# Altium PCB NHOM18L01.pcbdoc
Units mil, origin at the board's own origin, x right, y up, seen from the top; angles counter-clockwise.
Board outline 2892.2 x 1700 mil, 2 copper layers (Top Layer, Bottom Layer); 35 components, 50 nets, 178 pads, 21 vias.
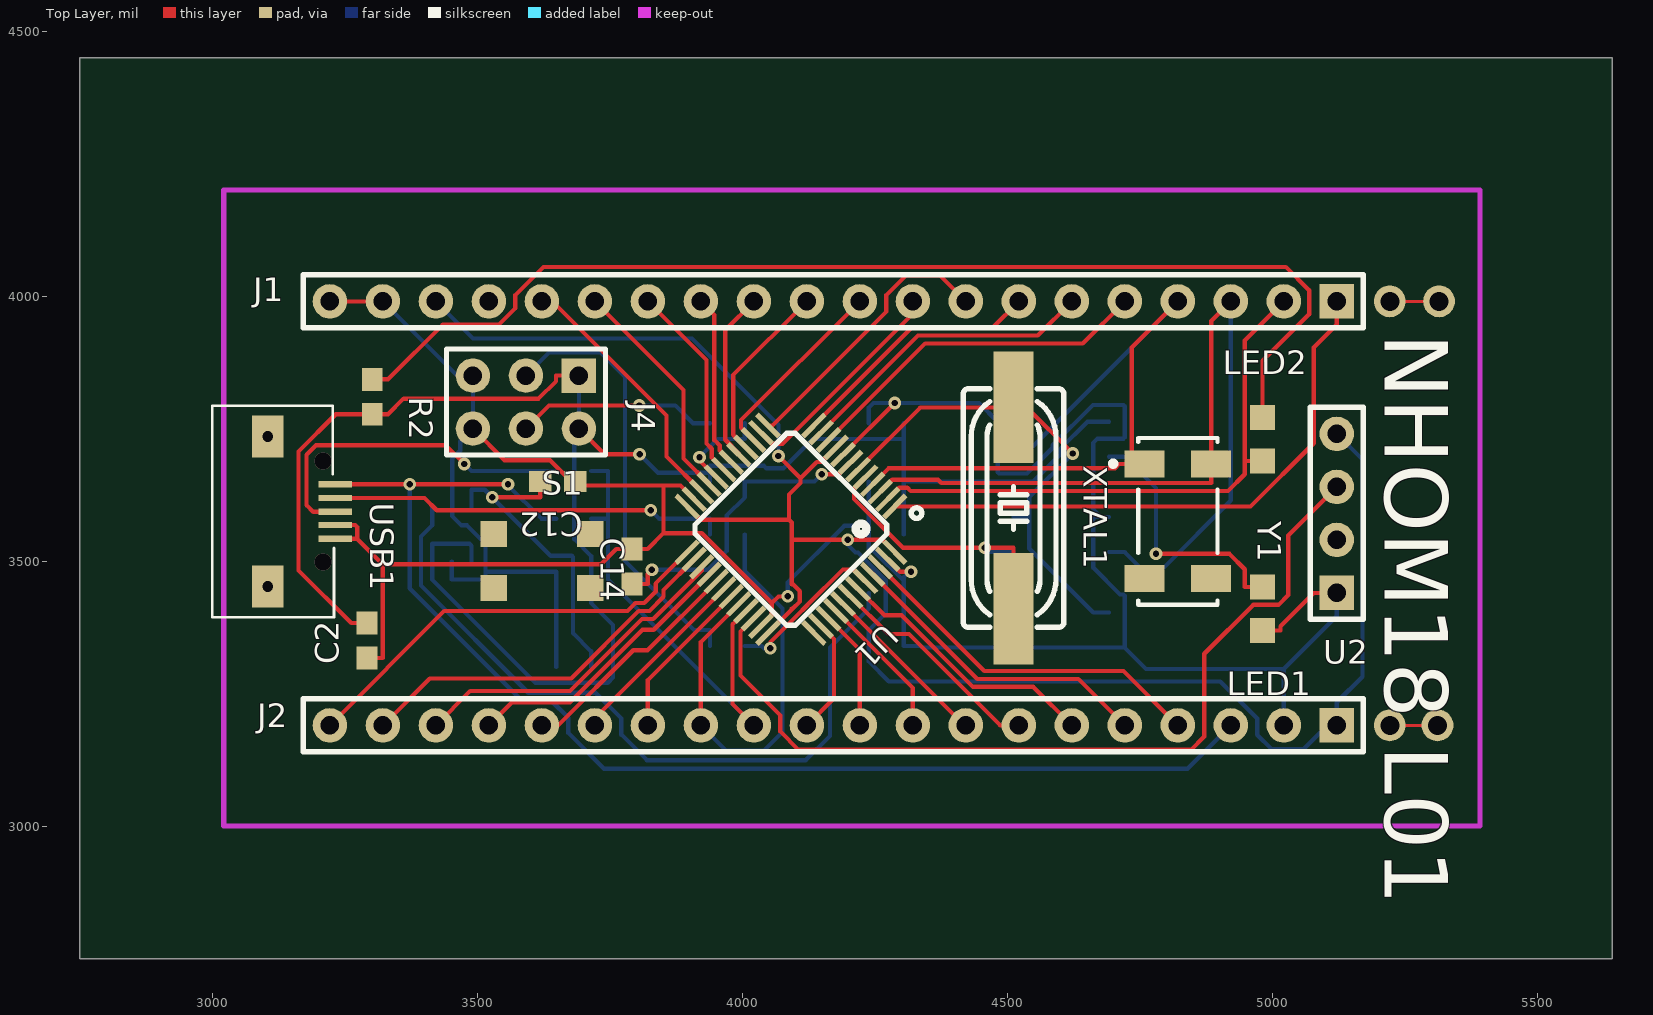
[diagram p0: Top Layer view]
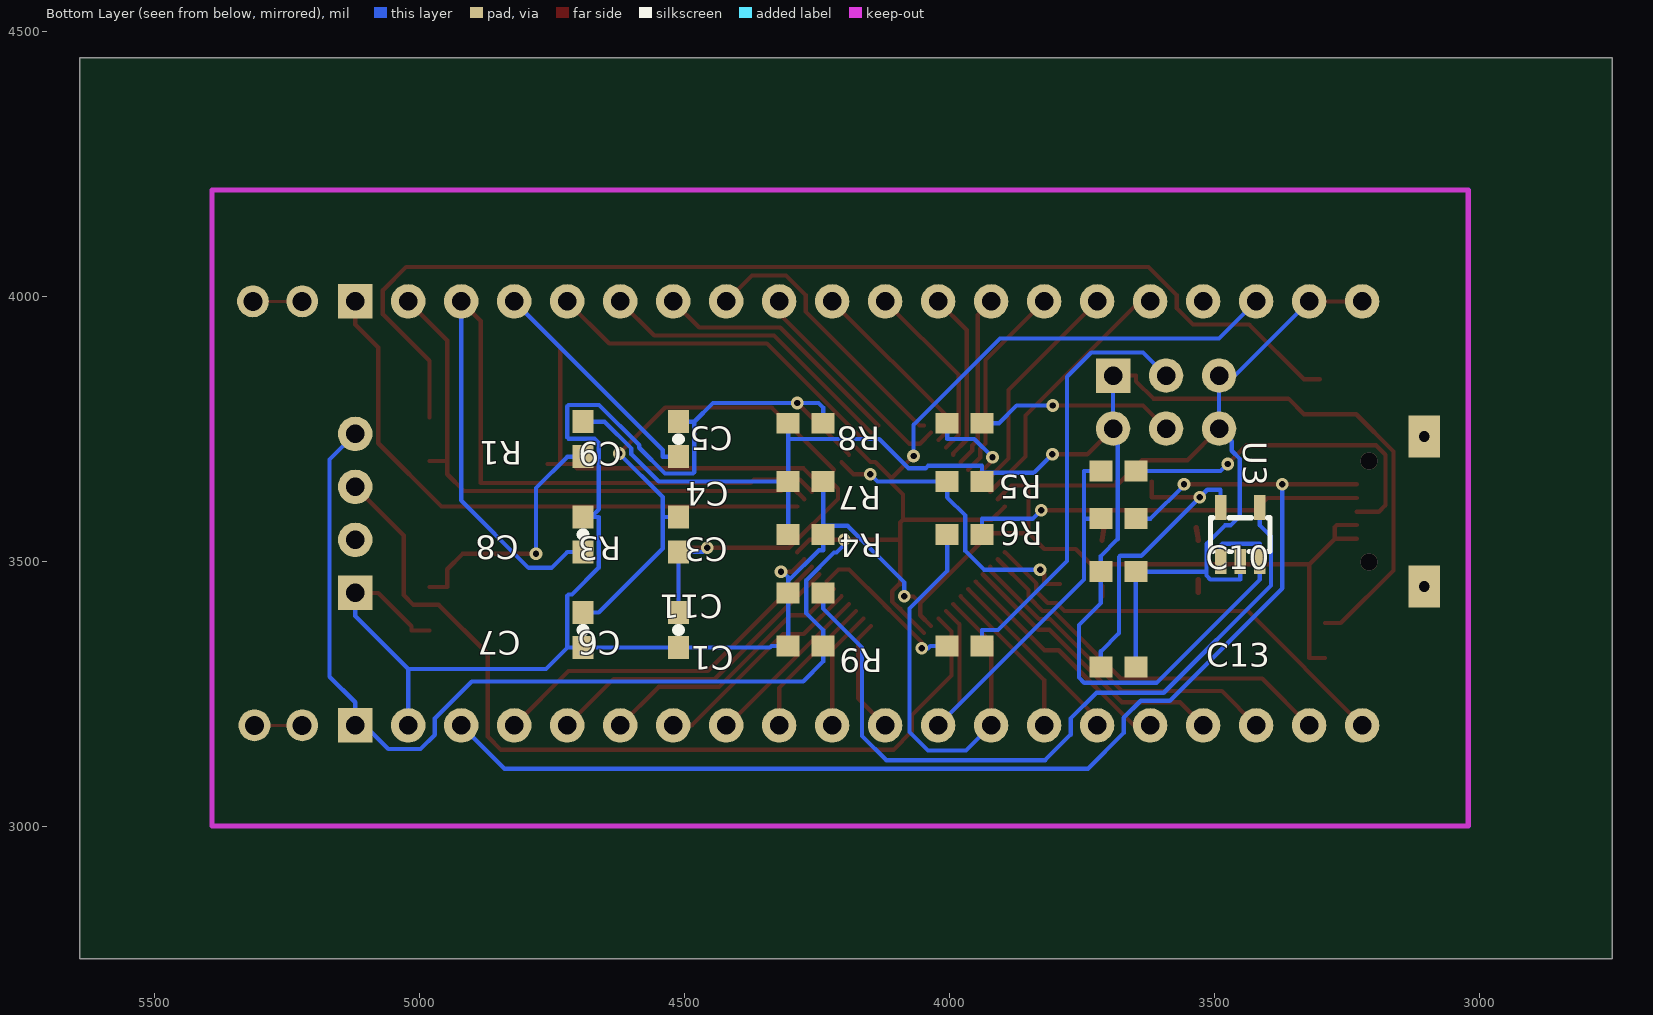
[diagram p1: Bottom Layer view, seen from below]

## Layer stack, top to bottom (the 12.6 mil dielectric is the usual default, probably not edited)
Top Layer: signal copper (thickness not stored)
Dielectric: dielectric 12.6, FR-4, Dk 4.8
Bottom Layer: signal copper (thickness not stored)

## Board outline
5642.2,2750 2750,2750 2750,4450 5642.2,4450

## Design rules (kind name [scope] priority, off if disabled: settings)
Clearance Default [All] p1: gap=7 ignorepadtopadclearanceinfootprint=FALSE except(0: Fill-Fill; 6: Track-Track Track-SMDPad SMDPad-SMDPad Track-THPad SMDPad-THPad THPad-THPad Track-Via SMDPad-Via THPad-Via Via-Via Track-Fill SMDPad-Fill THPad-Fill Via-Fill Track-Poly SMDPad-Poly THPad-Poly Via-Poly Fill-Poly Poly-Poly Track-Text SMDPad-Text THPad-Text Via-Text Fill-Text Poly-Text Text-Text Track-Hole SMDPad-Hole THPad-Hole Via-Hole Fill-Hole Poly-Hole Text-Hole)
DiffPairsRouting differentialPair [All] p1: maxuncoupledlength=10 minlimit=6 maxlimit=50 mostfreqgap=6 toplayer_minwidth=5 toplayer_prefwidth=10 toplayer_maxwidth=100 bottomlayer_minwidth=5 bottomlayer_prefwidth=10 bottomlayer_maxwidth=100
PasteMaskExpansion Common [All] p1:
PlaneConnect Default [All] p1: planeconnectstyle=Relief reliefexpansion=20 reliefentries=4 reliefconductorwidth=0 reliefairgap=10
PolygonConnect Default [All] p1: connectstyle=Relief reliefentries=4 polygonreliefangle="90 Angle" airgapwidth=10
RoutingVias Default [All] p1: viastyle="Through Hole" holewidth=12 minholewidth=12 maxholewidth=2362 width=24 minwidth=24 maxwidth=3938
SolderMaskExpansion Common [All] p1: useseparateexpansions=TRUE expansion=2 expansionbottom=2
Width Default [All] p1: maxlimit=1000 minlimit=6 preferedwidth=6

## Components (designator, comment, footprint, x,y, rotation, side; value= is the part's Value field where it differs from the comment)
C1 "100nF" 0603 4272.2,3340 r180 bottom
C2 "100nF" 0603 3292.2,3350 r90 top
C3 "100nF" 0603 4272.2,3550 r0 bottom
C4 "100nF" 0603 4272.2,3650 r0 bottom
C5 "100nF" 0603 4272.2,3760 r0 bottom
C6 "CAP" 0603-CAP 4512.2,3370 r90 bottom
C7 "CAP" 0603-CAP 4692.2,3370 r90 bottom
C8 "CAP" 0603-CAP 4692.2,3550 r270 bottom
C9 "CAP" 0603-CAP 4512.2,3730 r270 bottom
C10 "105" 0603 3682.2,3480 r180 bottom
C11 "223" 0603 4272.2,3440 r180 bottom
C12 "106" 0603 3652.2,3650 r180 top
C13 "104" 0603 3682.2,3300 r0 bottom
C14 "105" 0603 3792.2,3490 r270 top
J1 "HEADER-20P-2.54" H20-2.54 4172.2,3990 r270 top
J2 "HEADER-20P-2.54" H20-2.54 4172.2,3190 r270 top
J4 "F185-1203A1BSYA1" H2X3-2.54 3592.2,3800 r270 top
LED1 "LEDCHIPLED_0805" CHIPLED_0805 4982.2,3410 r180 top
LED2 "LEDCHIPLED_0805" CHIPLED_0805 4982.2,3730 r180 top
R1 "510Ω" 0603 4692.2,3730 r90 bottom
R2 "510Ω" 0603 3302.2,3810 r270 top
R3 "1M" 0603 4512.2,3550 r270 bottom
R4 "20R" 0603 3972.2,3550 r0 bottom
R5 "20R" 0603 3682.2,3670 r0 bottom
R6 "4.7K" 0603 3682.2,3580 r0 bottom
R7 "10K" 0603 3972.2,3650 r180 bottom
R8 "100K" 0603 3972.2,3760 r180 bottom
R9 "100K" 0603 3972.2,3340 r0 bottom
S1 "2P-SW-SMD" 2PSW-SMD 3622.2,3500 r0 top
U1 "IC_UC_STM32" LQFP48 4092.2,3560 r225 top
U2 "header4" H4-2.54 5122.2,3590 r180 top
U3 "RT9193-33GB" SOT-23-5 3452.2,3550 r180 bottom
USB1 "USB-Micro-1" MicroUSB 3202.2,3690 r270 top
XTAL1 "8M" HC-49U 4512.2,3600 r270 top
Y1 "RSM200S32.768" RSM200S 4822.2,3580 r270 top

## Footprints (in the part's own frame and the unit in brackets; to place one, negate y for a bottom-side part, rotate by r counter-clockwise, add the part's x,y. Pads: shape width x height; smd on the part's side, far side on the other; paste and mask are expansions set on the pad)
2PSW-SMD [mil]
  rect 50x25 smd: 1(-91,63) 2(91,63) 3(91,-63) 4(-91,-63) P$1(-91,39) P$2(91,39) P$3(91,-39) P$4(-91,-39)
  Top Layer lines w10: -91,-59 -91,-35 ; -91,39 -87,63 ; 87,63 91,39 ; 91,-67 91,-47
0603 [mil]
  rect 43.3x39.4 smd: 1(-33,0) 2(33,0)
0603-CAP [mil]
  rect 43.3x39.4 smd: 1(-33,0) 2(33,0)
  silkscreen extent 0,-1 0,1
CHIPLED_0805 [mil]
  rect 47.2x47.2 smd: A(0,-41) C(0,41)
H2X3-2.54 [mil]
  rect 65x65 hole 35: 1(-50,100)
  round 65 hole 35: 2(-50,0) 3(-50,-100) 4(50,-100) 5(50,0) 6(50,100)
  silkscreen extent -100,-150 100,150
H4-2.54 [mil]
  rect 65x65 hole 35: 1(0,150)
  round 65 hole 35: 2(0,50) 3(0,-50) 4(0,-150)
  silkscreen extent -50,-200 50,200
H20-2.54 [mil]
  rect 65x65 hole 35: 1(0,950)
  round 65 hole 35: 2(0,850) 3(0,750) 4(0,650) 5(0,550) 6(0,450) 7(0,350) 8(0,250) 9(0,150) 10(0,50) 11(0,-50) 12(0,-150) 13(0,-250) 14(0,-350) 15(0,-450) 16(0,-550) 17(0,-650) 18(0,-750) 19(0,-850) 20(0,-950)
  silkscreen extent -50,-1000 50,1000
HC-49U [mil]
  rect 210x76 smd: 1(-190,0) 2(190,0)
  silkscreen extent -225,-95 225,95
LQFP48 [mil]
  rect 59.1x10 smd: 1(-169,108.02) 2(-169.01,89.02) 3(-169.01,69.02) 4(-169,49.02) 5(-169.01,30.02) 6(-169.01,10.02) 7(-169.01,-9.98) 8(-169,-29.98) 9(-169.01,-48.98) 10(-169.01,-68.98) 11(-169,-88.98) 12(-169.01,-107.98) 25(169,-107.98) 26(169,-88.98) 27(169,-68.99) 28(169,-48.97) 29(169,-29.98) 30(169,-9.98) 31(168.99,10.02) 32(169,30.02) 33(169,49.02) 34(168.99,69.02) 35(169,89.02) 36(169,108.02)
  rect 10x59.1 smd: 13(-108,-168.98) 14(-89,-168.98) 15(-69.01,-168.98) 16(-49,-168.98) 17(-30,-168.98) 18(-10.01,-168.98) 19(10,-168.98) 20(30,-168.98) 21(49,-168.98) 22(69,-168.98) 23(89,-168.98) 24(108,-168.98) 37(108,169.02) 38(89,169.02) 39(68.99,169.02) 40(49,169.02) 41(30,169.02) 42(9.99,169.02) 43(-10.01,169.02) 44(-30,169.02) 45(-49,169.02) 46(-69.01,169.02) 47(-89,169.02) 48(-108,169.02)
  silkscreen extent -199,-134 134,156
MicroUSB [mil]
  rect 12x63 smd: 1(45,30) 2(71,30) 3(97,30) 4(122,30) 5(148,30)
  rect 79x59 hole 20: 6(-45,-97) 6(238,-97)
  silkscreen extent -103,-202 296,28
RSM200S [mil]
  rect 51.5x75.5 smd: 1(-103,-63) 2(113,-63) 3(113,63) 4(-103,63)
  silkscreen extent -152,-127 162,75
SOT-23-5 [mil]
  rect 21.7x47.2 smd: 1(-37,-51) 2(0,-51) 3(37,-51) 4(37,51) 5(-37,51)
  silkscreen extent -56,-32 56,32

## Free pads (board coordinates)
  round 60 hole 36: 1(5222.2,3190) 1(5222.2,3990) 2(5312.2,3190) 2(5315.06,3990)

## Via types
v1: diameter 24, hole 12, Top Layer to Bottom Layer, 19 vias
v2: diameter 31.5, hole 31.5, Top Layer to Bottom Layer, 2 vias

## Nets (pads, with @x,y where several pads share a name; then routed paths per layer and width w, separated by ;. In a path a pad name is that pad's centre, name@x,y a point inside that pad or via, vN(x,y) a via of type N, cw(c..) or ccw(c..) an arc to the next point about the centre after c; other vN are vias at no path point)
5V: J2.3 R6.1 USB1.1 | length 2382.8
  Top Layer w8: USB1.1 v1(3372.8,3645) v1(3558.4,3645)
  Bottom Layer w8: v1(3372.8,3645) 3372.8,3448.83 3585.09,3236.54 3639.98,3236.54 3672.2,3204.32 3672.2,3175.39 3739.53,3108.06 4840.26,3108.06 J2.3 ; v1(3558.4,3645) 3558.43,3642.92 3621.35,3580 3635.3,3580 3642.81,3580 3646.03,3580 R6.1
BOOT0: R9.2 U1.44 | length 307.4
  Top Layer w8: v1(4053.4,3335.5) 4053.4,3347.19 4101.59,3395.38 4101.75,3395.38 4124.01,3417.64 4124.01,3417.8 4190.48,3484.27 4210.38,3484.27 U1.44@4232.95,3461.7
  Bottom Layer w8: R9.2 4036.91,3340 4041.37,3335.54 v1(4053.4,3335.5)
BOOT1: R8.1 U1.20 | length 180.3
  Top Layer w8: v1(3919.8,3696.1) 3919.83,3689.92 U1.20@3951.5,3658.25
  Bottom Layer w8: v1(3919.8,3696.1) 3954.01,3730.29 4005.25,3730.29 R8.1
C13_2: C12.2 C13.2 U3.5 | length 620.2
  Top Layer w8: v1(3528.7,3620.3) 3619.25,3620.29 C12.2
  Bottom Layer w8: U3.5 3489.25,3634.61 3514.35,3634.61 v1(3528.7,3620.3) 3638.79,3510.17 3678.61,3510.17 3680.92,3507.86 3680.92,3364.04 3715.25,3329.71 C13.2
J4_2: J4.2 R9.1 | length 815.4
  Bottom Layer w8: J4.2 3635.72,3893.52 3733.39,3893.52 3779.12,3847.79 3779.12,3500.13 3909.54,3369.71 3939.25,3369.71 R9.1
J4_5: J4.5 R8.2 | length 379
  Top Layer w8: J4.5 3635.72,3793.52 v1(3805.8,3793.5)
  Bottom Layer w8: v1(3805.8,3793.5) 3874.07,3793.52 3907.59,3760 R8.2
LED1_A: LED1.A R1.1 | length 484.4
  Top Layer w8: v1(4781,3513.6) 4919.58,3513.62 4948.59,3484.61 4948.59,3451 LED1.A
  Bottom Layer w8: R1.1 4721.91,3696.95 4780.98,3637.88 v1(4781,3513.6)
OSCIN: C6.2 R3.2 U1.5 XTAL1.2 | length 681.9
  Top Layer w8: U1.5@4232.95,3658.25 4211.3,3636.6 4211.3,3617.36 4303.65,3525.01 v1(4457.8,3525) 4512.2,3525.01 XTAL1.2
  Bottom Layer w8: v1(4457.8,3525) 4465.84,3516.95 4482.49,3516.95 R3.2@4497.35,3516.95 ; C6.2 4512.2,3502.1 R3.2@4497.35,3516.95 ; R3.2 R3.2@4497.35,3516.95
OSCOUT: C7.2 R3.1 U1.6 XTAL1.1 | length 933.5
  Top Layer w8: U1.6 4336.38,3790 XTAL1.1 4537.09,3790 v1(4624.1,3703)
  Bottom Layer w8: R3.1 4541.91,3582.95 ; v1(4624.1,3703) 4541.91,3620.74 4541.91,3582.95 ; C7.2 4662.49,3402.95 4541.91,3523.53 4541.91,3582.95
PA0: J1.5 U1.10 | length 667.7
  Top Layer w8: U1.10@4162.95,3728.25 4345.44,3910.74 4642.94,3910.74 J1.5
PA1: J1.6 U1.11 | length 576
  Top Layer w8: U1.11 4332.11,3925.75 4557.95,3925.75 J1.6
PA2: J1.7 U1.12 | length 483.8
  Top Layer w8: U1.12@4135.35,3755.85 4320.26,3940.76 4472.96,3940.76 J1.7
PA3: J1.8 U1.13 | length 528.9
  Top Layer w8: U1.13@4049.08,3755.85 4057.21,3755.85 4272.2,3970.84 4272.2,4001.99 4309.16,4038.95 4373.25,4038.95 J1.8
PA4: J1.9 U1.14 | length 420.1
  Top Layer w8: U1.14 4056.88,3721.19 4076.2,3721.19 4322.2,3967.19 J1.9
PA5: J1.10 U1.15 | length 364.2
  Top Layer w8: U1.15@4021.53,3728.25 3998.17,3751.61 3998.17,3765.97 J1.10
PA6: J1.11 U1.16 | length 343.5
  Top Layer w8: U1.16@4007.35,3714.15 3983.15,3738.35 3983.15,3850.95 J1.11
PA7: J1.12 U1.17 | length 322.4
  Top Layer w8: U1.17@3993.95,3700.7 3993.95,3703.19 3968.13,3729.01 3968.13,3935.93 J1.12
PA8: J2.16 U1.29 | length 441.8
  Top Layer w8: J2.16 3652.9,3190 3794.69,3331.79 3821.59,3331.79 U1.29
PA9: J2.15 U1.30 | length 358.4
  Top Layer w8: J2.15 3722.2,3204.1 U1.30
PA10: J2.14 U1.31 | length 308.7
  Top Layer w8: J2.14 3822.2,3275.82 U1.31
PA11: J2.13 R4.2 U1.32 | length 849.3
  Top Layer w8: J2.13 3922.2,3347.5 U1.32@3993.95,3419.25
  Bottom Layer w8: J2.13 3969.71,3142.49 4041.34,3142.49 4076.46,3177.61 4076.46,3410.39 4005.25,3481.6 4005.25,3520.29 R4.2
PA12: J2.12 R5.2 R6.2 U1.33 | length 900.3
  Top Layer w8: U1.33 3982.09,3380.59 3982.09,3230.11 J2.12
  Bottom Layer w8: R6.2 3746.91,3580 ; R5.2 3746.91,3670 3746.91,3580 ; J2.12 3746.91,3465.29 3746.91,3580
PA15: J2.11 U1.38 | length 219
  Top Layer w8: J2.11 4173.46,3241.26 4173.46,3352.87 U1.38
PB0: J1.13 U1.18 | length 327.3
  Top Layer w8: J1.13 3947.72,3964.48 3947.72,3728.19 3957.85,3718.06 3957.85,3708.5 U1.18
PB1: J1.14 U1.19 | length 377
  Top Layer w8: J1.14 3932.65,3879.55 3932.65,3722.03 3942.84,3711.84 3942.84,3695.23 U1.19
PB3: J2.10 U1.39 | length 226.2
  Top Layer w8: U1.39@4162.95,3391.7 4222.2,3332.45 J2.10
PB4: J2.9 U1.40 | length 276
  Top Layer w8: U1.40@4177.05,3405.85 4322.2,3260.7 J2.9
PB5: J2.8 U1.41 | length 326.7
  Top Layer w8: U1.41@4190.5,3419.25 4419.75,3190 J2.8
PB6: J2.7 U1.42 | length 418.4
  Top Layer w8: U1.42 4275.9,3362.17 4315.13,3362.16 4487.29,3190 J2.7
PB7: J2.6 U1.43 | length 510.1
  Top Layer w8: U1.43 4268.54,3397.81 4300.71,3397.81 4435.83,3262.69 4549.51,3262.69 J2.6
PB8: J2.5 U1.45 | length 594
  Top Layer w8: U1.45@4246.35,3475.15 4443.8,3277.7 4634.5,3277.7 J2.5
PB9: J2.4 U1.46 | length 685.6
  Top Layer w8: U1.46@4260.53,3489.25 4457.07,3292.71 4719.49,3292.71 J2.4
PB10: J1.15 U1.21 | length 434.6
  Top Layer w8: J1.15 3889.45,3822.75 3889.45,3693.45 U1.21@3938.05,3644.85
PB11: J1.16 U1.22 | length 496
  Top Layer w8: J1.16 3642.18,3990 3857.41,3774.77 3857.41,3697.24 U1.22@3923.95,3630.7
PB12: J2.20 U1.25 | length 818.5
  Top Layer w8: J2.20 3437.88,3405.68 3783.62,3405.68 3798.65,3420.71 3815.5,3420.71 3836.93,3442.14 3836.93,3457.43 U1.25
PB13: J2.19 U1.26 | length 725
  Top Layer w8: J2.19 3410.74,3278.54 3677.71,3278.54 3804.87,3405.7 3825.09,3405.7 3851.95,3432.56 3851.95,3445.62 U1.26
PB14: J2.18 U1.27 | length 629.8
  Top Layer w8: J2.18 3486.94,3254.74 3675.14,3254.74 3811.09,3390.69 3832.32,3390.69 3923.95,3482.32 U1.27@3923.95,3489.25
PB15: J2.17 U1.28 | length 534
  Top Layer w8: J2.17 3565.71,3233.51 3675.14,3233.51 3811.99,3370.36 3833.26,3370.36 U1.28@3938.05,3475.15
PC13: J1.2 LED2.C U1.2 | length 1088.9
  Top Layer w8: U1.2 4296.45,3638.35 4311.88,3638.35 4318.06,3632.17 4916.97,3632.17 4948.59,3663.79 4948.59,3689 ; LED2.C 4948.59,3689 ; J1.2 4948.59,3916.39 4948.59,3689
PC14: C8.2 J1.3 U1.3 Y1.4 | length 1665.2
  Top Layer w8: U1.3 4283.2,3653.37 4369.76,3653.37 4375.94,3647.19 4885.2,3647.19 4885.2,3665.07 Y1.4 4885.2,3953 J1.3
  Bottom Layer w8: C8.2 4721.91,3516.95 4751.62,3487.24 4794.85,3487.24 4922.2,3614.59 J1.3
PC15: C9.2 J1.4 U1.4 Y1.1 | length 1310.6
  Top Layer w8: U1.4 4276.49,3674.99 4703.53,3674.99 4711.49,3682.95 Y1.1@4735.37,3682.95 ; Y1.1 Y1.1@4735.37,3682.95 ; J1.4 4735.37,3903.17 Y1.1@4735.37,3682.95
  Bottom Layer w8: C9.2 4541.91,3696.95 4541.91,3709.71 J1.4
R2_1: LED2.A R2.1 | length 2164.5
  Top Layer w8: R2.1 3331.91,3842.95 3435.44,3946.48 3541.47,3946.48 3572.2,3977.21 3572.2,4001.81 3625.25,4054.86 5026.07,4054.86 5069.98,4010.95 5069.98,3965.78 4982.2,3878 LED2.A
R5_1: R5.1 USB1.3 | length 653
  Top Layer w8: USB1.3 3190.69,3593 3178.16,3605.53 3178.16,3700.56 3196.21,3718.61 3440.63,3718.61 v1(3476,3683.2)
  Bottom Layer w8: v1(3476,3683.2) 3489.24,3670 R5.1
RESET: C14.2 R7.1 S1.3 U1.7 | length 575.1
  Top Layer w8: C14.2 3821.91,3456.95 3821.91,3475.78 v1(3829.9,3483.8) ; v1(4150.5,3663.9) 4181.96,3663.86 U1.7
  Bottom Layer w8: v1(3829.9,3483.8) 3935.6,3483.81 3970.92,3519.13 3970.92,3585.96 4005.25,3620.29 R7.1 4136.6,3650 v1(4150.5,3663.9)
SWDIO: U1.34 U2.3 | length 1681.9
  Top Layer w8: U1.34 3997.11,3367.28 3997.11,3283.86 4072.2,3208.77 4072.2,3178.19 4106.55,3143.84 4847.23,3143.84 4872.2,3168.81 4872.2,3325.15 4964.43,3417.38 5012.01,3417.38 5030.64,3436.01 5030.64,3548.44 U2.3
U3_4: C11.2 U3.4 | length 1400.9
  Bottom Layer w8: U3.4 3415.25,3567.39 3394.39,3546.53 3394.39,3453.74 3596.57,3251.56 3723.66,3251.56 3772.2,3203.02 3772.2,3172.51 3820.34,3124.37 4120.15,3124.37 4165.72,3169.94 4165.72,3336.76 4239.25,3410.29 C11.2
USB1_2: R4.1 USB1.2 | length 753
  Top Layer w8: USB1.2 3400.91,3619 3423.88,3596.03 v1(3827.6,3596)
  Bottom Layer w8: v1(3827.6,3596) 3843.9,3579.71 3939.25,3579.71 R4.1
VBAT: J1.1 U1.1 | length 1125.7
  Top Layer w8: U1.1 4959.45,3603.12 5078.69,3722.36 5078.69,3902.98 5122.2,3946.49 J1.1
VCC: C2.2 C3.2 C4.2 C5.2 C10.1 J4.1 J4.6 R1.2 R2.2 R7.2 U3.1 U3.3 | length 3543.8
  Top Layer w8: C2.2 3262.49,3382.95 3163.15,3482.29 3163.15,3706.78 3233.32,3776.95 R2.2 3331.91,3776.95 3361.45,3806.49 3616.07,3806.49 3648.69,3839.11 3648.69,3850 J4.1 ; J4.6 3740.74,3701.46 v1(3806.6,3701.5)
  Bottom Layer w8: U3.1 3489.25,3528.85 3485.49,3532.61 3415.25,3532.61 3415.25,3515.8 U3.3 3415.25,3465.39 3610.36,3270.28 3746.5,3270.28 3756.43,3280.21 3756.43,3379.5 3715.25,3420.68 C10.1 3715.25,3483.17 3715.25,3509.71 3683.56,3541.4 3683.56,3741.36 J4.6 3692.2,3806.49 J4.1 ; v1(3806.6,3701.5) 3841.41,3666.69 R7.2@3939.25,3666.69 ; R7.2 R7.2@3939.25,3666.69 ; C3.2 C4.2 ; C5.2 4305.25,3730.29 ; R1.2 4662.49,3762.95 4651.58,3762.95 4601.12,3712.49 4601.12,3701.58 4549.54,3650 C4.2 ; R7.2@3939.25,3666.69 3939.25,3679.71 4041.25,3679.71 4045.79,3675.17 4078.13,3675.17 4133.25,3730.29 4305.25,3730.29 ; C4.2 4305.25,3730.29
VCC3V3: 
pads on no net: C1.1 C1.2 C2.1 C3.1 C4.1 C5.1 C6.1 C7.1 C8.1 C9.1 C10.2 C11.1 C12.1 C13.1 C14.1 J1.17 J1.18 J1.19 J1.20 J2.1 J2.2 J4.3 J4.4 LED1.C S1.1 S1.2 S1.4 S1.P$1 S1.P$2 S1.P$3 S1.P$4 U1.8 U1.9 U1.23 U1.24 U1.35 U1.36 U1.37 U1.47 U1.48 U2.1 U2.2 U2.4 U3.2 USB1.4 USB1.5 USB1.6 Y1.2 Y1.3
copper on no net: | length 10027.5
  Top Layer w6: 5222.2,3190 5312.2,3190 ; 5222.2,3990 5315.06,3990
  Top Layer w8: 3222.2,3990 3322.2,3990 ; 3232.2,3542 3273.71,3542 ; 3232.2,3568 3269.96,3568 3273.71,3564.25 3273.71,3542 ; 3292.2,3316.95 3321.91,3316.95 3321.91,3493.8 ; 3492.2,3750 3551.86,3690.34 3637.48,3690.34 3685.25,3642.57 ; 3685.25,3650 3685.25,3642.57 ; 3896.35,3603.12 3921.4,3578.07 4088.58,3578.07 ; 3909.75,3616.55 3883.73,3642.57 3851.62,3642.57 ; 4035.65,3377.55 4055.91,3397.81 4055.91,3420.59 ; 4049.08,3364.12 4093.62,3408.66 4093.62,3410.39 4095.53,3410.39 4109,3423.86 4109,3442.94 4095.53,3456.41 4093.62,3456.41 4093.62,3540.2 ; v1(4068.6,3698.2) 4110.42,3656.35 ; v1(4086,3433.4) 4068.72,3433.4 4055.91,3420.59 ; 4177.05,3714.15 4149.77,3686.87 4140.93,3686.87 4110.42,3656.35 ; 4190.5,3700.7 4190.5,3700.81 v1(4288,3798.3) ; 4274.65,3503.42 4298.37,3479.7 v1(4318.7,3479.7) ; 4288.08,3516.85 4264.73,3540.2 v1(4199.2,3540.2) 4093.62,3540.2 ; 4982.2,3369 5015.81,3369 5015.81,3377.12 5078.69,3440 5122.2,3440 ; 3273.71,3542 3321.91,3493.8 ; 3321.91,3493.8 3733.34,3493.8 3762.49,3522.95 3777.35,3522.95 3792.2,3522.95 3821.91,3522.95 3851.62,3552.66 ; 3685.25,3642.57 3851.62,3642.57 ; 3851.62,3552.66 3923.84,3552.66 4055.91,3420.59 ; 3851.62,3552.66 3851.62,3642.57 ; 4088.58,3578.07 4088.58,3625.68 4110.42,3647.52 4110.42,3656.35 ; 4088.58,3578.07 4093.62,3573.03 4093.62,3540.2
  Bottom Layer w8: 3322.2,3990 3462.2,3850 3492.2,3850 3492.2,3750 3468.38,3726.18 3468.38,3708.17 ; 3422.2,3990 3492.2,3920 3905.67,3920 4068.59,3757.08 v1(4068.6,3698.2) ; 3452.25,3499 3452.25,3465.39 3508.7,3465.39 3516,3472.69 3516,3480 ; 3468.37,3708.17 3452.98,3692.78 3452.98,3585.11 3470.71,3567.38 3481.12,3567.38 3516,3532.5 3516,3480 ; 3649.25,3300 3649.25,3329.71 3649.25,3450.29 3649.25,3480 3617.59,3480 3516,3480 ; v1(4086,3433.4) 4085.99,3459.58 4193.01,3566.6 4239.25,3566.6 ; v1(4199.2,3540.2) 4199.15,3531.05 4214.07,3516.13 4218.62,3516.13 4270.92,3463.83 4270.92,3401.38 4239.25,3369.71 4239.25,3340 4239.25,3310.29 4276.82,3272.72 4902.3,3272.72 4972.2,3202.82 4972.2,3172.12 4998.83,3145.49 5059.69,3145.49 5122.2,3208 ; 4239.25,3650 4239.25,3566.6 ; 4239.25,3760 4239.25,3789.71 4247.85,3798.31 v1(4288,3798.3) 4447.13,3798.31 4482.49,3762.95 ; v1(4318.7,3479.7) 4315.24,3479.7 4305.25,3469.71 4305.25,3462.28 ; 4512.2,3762.95 4482.49,3762.95 ; 4692.2,3582.95 4677.35,3582.95 ; 5022.2,3190 5022.2,3296.49 ; 5122.2,3190 5122.2,3208 ; 5122.2,3440 5122.2,3396.49 5022.2,3296.49 ; 5122.2,3740 5170.51,3691.69 5170.51,3281.82 5122.2,3233.51 5122.2,3208 ; 4239.25,3566.6 4239.25,3550 4239.25,3520.29 4247.24,3520.29 4305.25,3462.28 ; 4305.25,3462.28 4305.25,3454.85 4305.25,3440 4305.25,3340 4336.91,3340 4339.96,3336.95 4512.2,3336.95 4692.2,3336.95 4707.06,3336.95 4721.91,3336.95 ; 4482.49,3762.95 4482.49,3667.6 4484.81,3665.28 4537.53,3665.28 4586.11,3713.86 4586.11,3718.71 4662.02,3794.62 4719.59,3794.62 4721.92,3792.29 4721.92,3733.28 4719.59,3730.95 4670.7,3730.95 4662.48,3722.73 4662.48,3597.82 4677.35,3582.95 ; 4677.35,3582.95 4662.49,3582.95 4662.49,3487.6 4713.23,3436.86 4719.58,3436.86 4721.91,3434.53 4721.91,3336.95 ; 4721.91,3336.95 4762.37,3296.49 5022.2,3296.49
  other v2: 3209.2,3498.1 3209.2,3689

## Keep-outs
Board Outline Layer:
  lines w10: 3022.2,3000 5392.2,3000 5392.2,4200 3022.2,4200 3022.2,3000

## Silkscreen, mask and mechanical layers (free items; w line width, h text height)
Top Silkscreen Layer:
  text "GND GND 3V3 NRS PB11 B10 PB1 PB0 PA7 A6 PA5 PA4 PA3 A2 PA1 PA0 C15 C14 C13 VBAT" at 3145,4085 h51
  text "NHOM18 L01" at 5212.2,3930 h120 r270
  text "B12 B13 B14 B15 PA8 PA9 A10 A11 A12 A15 PB3 PB4 PB5 PB6 PB7 PB8 PB9 5V GND 3V3" at 3180,3060 h51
